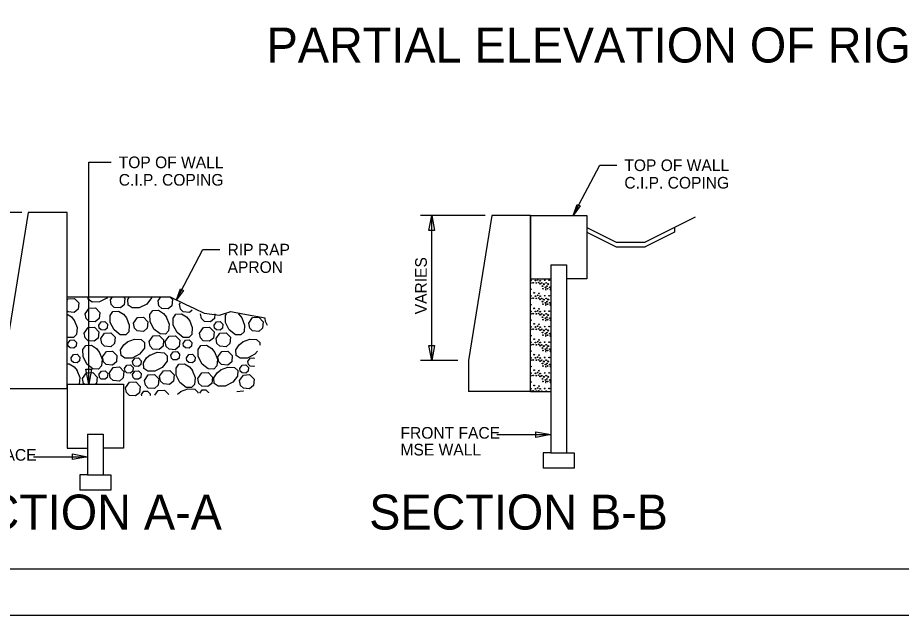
# Model space of a CAD drawing. Extents: x 96 to 240, y 601 to 689.
# Drawn here: x 115.15 to 153.07, y 601 to 626.64 of the extents above; entities that cross this region are included whole.
import ezdxf

# ---------------------------------------------------------------- set-up
doc = ezdxf.new("R2010")
doc.units = 0
for name, color, linetype in [('BR_AUTO DIMENSION', 7, 'Continuous'), ('BR_BORDER LINES', 7, 'Continuous'), ('BR_CONCRETE', 7, 'Continuous'), ('BR_DETAILS', 7, 'Continuous'), ('BR_TEXT', 7, 'Continuous'), ('Level 31', 7, 'Continuous')]:
    doc.layers.add(name, color=color, linetype=linetype)

# ---------------------------------------------------------------- blocks, each defined once
blk = doc.blocks.new('B')
at = {"layer": 'BR_AUTO DIMENSION'}
blk.add_lwpolyline([(-0.2, 0.03), (0, 0), (-0.2, -0.03)], close=True, dxfattribs=at)
blk = doc.blocks.new('ARROW')
at = {"layer": 'BR_AUTO DIMENSION', "xscale": 0.625, "yscale": 0.625}
blk.add_blockref('B', (0, 0), dxfattribs=at)

msp = doc.modelspace()

# ---------------------------------------------------------------- linework, layer by layer
at = {"layer": 'BR_AUTO DIMENSION'}
for p, q in [((118.201, 620.439), (119.163, 620.439)), ((118.201, 610.916), (118.201, 620.439)), ((138.992, 618.156), (140.125, 620.314)), ((140.125, 620.314), (140.856, 620.314)), ((115.328, 618.281), (112.555, 618.281)), ((135.211, 618.156), (132.438, 618.156)), ((132.919, 611.933), (132.919, 618.156)), ((121.969, 614.535), (123.102, 616.693)), ((123.102, 616.693), (123.833, 616.693)), ((134.04, 611.933), (132.438, 611.933)), ((135.718, 608.755), (138.035, 608.755)), ((115.835, 607.809), (118.151, 607.809))]:
    msp.add_line(p, q, dxfattribs=at)
for points in [[(132.794, 617.506), (132.919, 618.156), (133.044, 617.506)], [(133.044, 612.583), (132.919, 611.933), (132.794, 612.583)], [(118.326, 611.566), (118.201, 610.916), (118.076, 611.566)], [(137.385, 608.88), (138.035, 608.755), (137.385, 608.63)], [(117.501, 607.934), (118.151, 607.809), (117.501, 607.684)]]:
    msp.add_lwpolyline(points, close=True, dxfattribs=at)
at = {"layer": 'BR_BORDER LINES'}
msp.add_line((103.173, 603.003), (237.837, 603.003), dxfattribs=at)
at = {"layer": 'BR_CONCRETE'}
for p, q in [((115.608, 618.281), (114.608, 612.058)), ((117.274, 618.281), (115.608, 618.281)), ((117.274, 610.725), (117.274, 618.281)), ((135.491, 618.156), (134.491, 611.933)), ((137.158, 618.156), (135.491, 618.156)), ((137.158, 610.6), (137.158, 618.156)), ((137.158, 618.156), (137.158, 615.437)), ((137.162, 618.156), (139.578, 618.156)), ((139.578, 618.156), (139.578, 615.437)), ((144.222, 618.089), (142.078, 617.017)), ((139.578, 617.642), (140.828, 617.017)), ((143.328, 617.642), (143.328, 617.434)), ((139.578, 617.434), (140.828, 616.809)), ((143.328, 617.434), (142.078, 616.809)), ((140.828, 617.017), (142.078, 617.017)), ((140.828, 616.809), (142.078, 616.809)), ((138.035, 616.041), (138.035, 607.981)), ((138.035, 616.041), (138.701, 616.041)), ((138.701, 616.041), (138.701, 607.981)), ((137.158, 615.437), (138.035, 615.437)), ((139.578, 615.437), (138.701, 615.437)), ((134.491, 611.933), (134.491, 610.6)), ((117.274, 610.916), (119.695, 610.916)), ((117.274, 610.916), (117.274, 608.173)), ((119.695, 610.916), (119.695, 608.173)), ((117.274, 610.725), (114.608, 610.725)), ((137.158, 610.6), (134.491, 610.6)), ((137.158, 610.6), (138.035, 610.6)), ((118.151, 608.777), (118.151, 607.036)), ((118.151, 608.777), (118.818, 608.777)), ((118.818, 608.777), (118.818, 607.036)), ((117.274, 608.173), (118.151, 608.173)), ((119.695, 608.173), (118.818, 608.173)), ((138.035, 607.981), (137.701, 607.981)), ((137.701, 607.981), (137.701, 607.314)), ((138.035, 607.981), (138.701, 607.981)), ((138.701, 607.981), (139.035, 607.981)), ((139.035, 607.981), (139.035, 607.314)), ((118.151, 607.036), (117.818, 607.036)), ((117.818, 607.036), (117.818, 606.369)), ((118.151, 607.036), (118.818, 607.036)), ((118.818, 607.036), (119.151, 607.036)), ((119.151, 607.036), (119.151, 606.369)), ((139.035, 607.314), (137.701, 607.314)), ((119.151, 606.369), (117.818, 606.369))]:
    msp.add_line(p, q, dxfattribs=at)
at = {"layer": 'BR_DETAILS'}
msp.add_line((143.26, 617.4), (143.264, 617.408), dxfattribs=at)
at = {"layer": 'BR_TEXT'}
for p, q in [((117.281, 614.664), (118.364, 614.664)), ((118.364, 614.664), (119.235, 614.664)), ((119.133, 614.54), (119.224, 614.67)), ((119.235, 614.664), (119.703, 614.664)), ((119.703, 614.664), (119.954, 614.664)), ((119.954, 614.664), (121.703, 614.664)), ((121.178, 614.493), (121.302, 614.67)), ((121.703, 614.664), (122.335, 614.359)), ((122.097, 614.347), (122.138, 614.406)), ((122.335, 614.359), (122.746, 614.16)), ((122.746, 614.16), (123.157, 613.961)), ((123.002, 613.94), (123.002, 613.941)), ((123.157, 613.961), (123.817, 613.884)), ((123.817, 613.884), (124.306, 614.032)), ((124.306, 614.032), (124.808, 613.941)), ((124.808, 613.941), (125.773, 613.766)), ((120.479, 610.42), (120.469, 610.471)), ((122.014, 610.492), (122.16, 610.609))]:
    msp.add_line(p, q, dxfattribs=at)
for points in [[(117.274, 614.524), (117.318, 614.586), (117.586, 614.601), (117.773, 614.408), (117.746, 614.137), (117.58, 613.999), (117.315, 614.018), (117.274, 614.058)], [(119.028, 614.67), (118.981, 614.611), (118.659, 614.45), (118.356, 614.444), (118.185, 614.566), (118.178, 614.67)], [(119.689, 614.67), (119.756, 614.601), (119.729, 614.33), (119.563, 614.192), (119.298, 614.212), (119.173, 614.333), (119.133, 614.54)], [(120.898, 614.67), (120.897, 614.623), (120.689, 614.357), (120.367, 614.196), (120.064, 614.19), (119.893, 614.312), (119.877, 614.553), (119.952, 614.67)], [(121.689, 614.67), (121.801, 614.554), (121.774, 614.283), (121.608, 614.146), (121.343, 614.165), (121.218, 614.286), (121.178, 614.493)], [(118.055, 613.94), (118.223, 614.18), (118.491, 614.195), (118.678, 614.001), (118.651, 613.73), (118.485, 613.593), (118.22, 613.612), (118.096, 613.733), (118.055, 613.94)], [(122.641, 614.094), (122.527, 613.999), (122.262, 614.018), (122.137, 614.139), (122.097, 614.347)], [(117.274, 613.924), (117.459, 613.806), (117.585, 613.647)], [(119.819, 613.772), (119.944, 613.457), (119.919, 613.168), (119.788, 613.031), (119.554, 613.036), (119.288, 613.244), (119.127, 613.566), (119.121, 613.869), (119.243, 614.04), (119.485, 614.056), (119.701, 613.918), (119.827, 613.759)], [(121.527, 613.812), (121.652, 613.498), (121.627, 613.209), (121.497, 613.072), (121.262, 613.076), (120.996, 613.285), (120.835, 613.607), (120.83, 613.91), (120.951, 614.081), (121.193, 614.097), (121.409, 613.958), (121.535, 613.8)], [(122.524, 613.66), (122.648, 613.345), (122.624, 613.057), (122.493, 612.919), (122.259, 612.924), (121.992, 613.132), (121.831, 613.454), (121.826, 613.757), (121.947, 613.928), (122.189, 613.944), (122.405, 613.806), (122.532, 613.647)], [(123.619, 613.941), (123.598, 613.73), (123.432, 613.593), (123.167, 613.612), (123.042, 613.733), (123.002, 613.94)], [(124.766, 613.772), (124.891, 613.457), (124.866, 613.168), (124.735, 613.031), (124.501, 613.036), (124.235, 613.244), (124.074, 613.566), (124.068, 613.869), (124.119, 613.941)], [(124.611, 613.941), (124.647, 613.918), (124.774, 613.759)], [(117.577, 613.66), (117.702, 613.345), (117.677, 613.057), (117.546, 612.919), (117.312, 612.924), (117.274, 612.953)], [(118.632, 613.451), (118.733, 613.594), (118.894, 613.603), (119.006, 613.487), (118.99, 613.325), (118.891, 613.242), (118.732, 613.253), (118.657, 613.326), (118.633, 613.451)], [(120.121, 613.534), (120.289, 613.773), (120.558, 613.788), (120.744, 613.595), (120.717, 613.324), (120.551, 613.186), (120.286, 613.205), (120.162, 613.326), (120.121, 613.534)], [(123.579, 613.451), (123.68, 613.594), (123.841, 613.603), (123.953, 613.487), (123.937, 613.325), (123.837, 613.242), (123.678, 613.253), (123.604, 613.326), (123.579, 613.451)], [(125.068, 613.534), (125.236, 613.773), (125.504, 613.788), (125.691, 613.595), (125.664, 613.324), (125.498, 613.186), (125.233, 613.205), (125.109, 613.326), (125.068, 613.534)], [(125.87, 613.431), (125.782, 613.607), (125.779, 613.748)], [(118.008, 613.11), (118.176, 613.349), (118.444, 613.365), (118.631, 613.171), (118.604, 612.9), (118.438, 612.762), (118.173, 612.782), (118.048, 612.902), (118.008, 613.11)], [(118.718, 612.873), (118.886, 613.112), (119.154, 613.127), (119.341, 612.934), (119.314, 612.663), (119.148, 612.525), (118.883, 612.544), (118.759, 612.665), (118.718, 612.873)], [(122.955, 613.11), (123.123, 613.349), (123.391, 613.365), (123.578, 613.171), (123.551, 612.9), (123.385, 612.762), (123.12, 612.782), (122.995, 612.902), (122.955, 613.11)], [(123.665, 612.873), (123.833, 613.112), (124.101, 613.127), (124.288, 612.934), (124.261, 612.663), (124.095, 612.525), (123.83, 612.544), (123.705, 612.665), (123.665, 612.873)], [(117.303, 612.67), (117.404, 612.814), (117.565, 612.823), (117.677, 612.707), (117.661, 612.544), (117.561, 612.462), (117.402, 612.473), (117.327, 612.546), (117.303, 612.67)], [(119.856, 612.733), (120.171, 612.857), (120.46, 612.832), (120.597, 612.702), (120.592, 612.467), (120.384, 612.201), (120.062, 612.04), (119.759, 612.035), (119.588, 612.156), (119.572, 612.398), (119.71, 612.614), (119.869, 612.741)], [(120.794, 612.754), (120.962, 612.994), (121.23, 613.009), (121.417, 612.815), (121.39, 612.544), (121.224, 612.407), (120.959, 612.426), (120.834, 612.547), (120.794, 612.754)], [(121.485, 612.744), (121.653, 612.983), (121.922, 612.999), (122.108, 612.805), (122.081, 612.534), (121.915, 612.396), (121.65, 612.416), (121.526, 612.536), (121.485, 612.744)], [(122.25, 612.67), (122.351, 612.814), (122.512, 612.823), (122.624, 612.707), (122.607, 612.544), (122.508, 612.462), (122.349, 612.473), (122.274, 612.546), (122.25, 612.67)], [(125.441, 612.342), (125.331, 612.201), (125.009, 612.04), (124.705, 612.035), (124.535, 612.156), (124.518, 612.398), (124.657, 612.614), (124.816, 612.741)], [(124.803, 612.733), (125.117, 612.857), (125.406, 612.832), (125.544, 612.702), (125.542, 612.598)], [(118.65, 612.308), (118.775, 611.993), (118.75, 611.704), (118.619, 611.567), (118.385, 611.571), (118.118, 611.78), (117.958, 612.102), (117.952, 612.405), (118.074, 612.576), (118.315, 612.592), (118.531, 612.454), (118.658, 612.295)], [(118.793, 612.086), (118.961, 612.325), (119.229, 612.341), (119.416, 612.147), (119.389, 611.876), (119.223, 611.738), (118.958, 611.758), (118.833, 611.878), (118.793, 612.086)], [(120.832, 612.171), (121.146, 612.296), (121.435, 612.271), (121.572, 612.14), (121.568, 611.906), (121.36, 611.639), (121.038, 611.478), (120.734, 611.473), (120.563, 611.594), (120.547, 611.836), (120.686, 612.052), (120.844, 612.179)], [(121.73, 612.166), (121.831, 612.309), (121.992, 612.319), (122.103, 612.203), (122.087, 612.04), (121.988, 611.957), (121.829, 611.969), (121.754, 612.041), (121.73, 612.166)], [(123.597, 612.308), (123.721, 611.993), (123.696, 611.704), (123.566, 611.567), (123.332, 611.571), (123.065, 611.78), (122.904, 612.102), (122.899, 612.405), (123.02, 612.576), (123.262, 612.592), (123.478, 612.454), (123.605, 612.295)], [(123.74, 612.086), (123.908, 612.325), (124.176, 612.341), (124.363, 612.147), (124.336, 611.876), (124.17, 611.738), (123.905, 611.758), (123.78, 611.878), (123.74, 612.086)], [(117.445, 612.048), (117.546, 612.191), (117.707, 612.2), (117.819, 612.084), (117.803, 611.922), (117.703, 611.839), (117.544, 611.851), (117.469, 611.923), (117.445, 612.048)], [(120.083, 611.89), (120.183, 612.034), (120.344, 612.043), (120.456, 611.927), (120.44, 611.764), (120.341, 611.681), (120.182, 611.693), (120.107, 611.765), (120.083, 611.89)], [(122.392, 612.048), (122.493, 612.191), (122.654, 612.2), (122.766, 612.084), (122.749, 611.922), (122.65, 611.839), (122.491, 611.851), (122.416, 611.923), (122.392, 612.048)], [(125.029, 611.89), (125.13, 612.034), (125.291, 612.043), (125.318, 612.015)], [(117.274, 611.793), (117.364, 611.799), (117.58, 611.661), (117.707, 611.502)], [(119.089, 611.402), (119.257, 611.641), (119.525, 611.657), (119.712, 611.463), (119.685, 611.192), (119.519, 611.054), (119.254, 611.074), (119.129, 611.194), (119.089, 611.402)], [(119.736, 611.599), (119.837, 611.742), (119.998, 611.751), (120.11, 611.635), (120.093, 611.473), (119.994, 611.39), (119.835, 611.401), (119.76, 611.474), (119.736, 611.599)], [(122.646, 611.514), (122.77, 611.2), (122.745, 610.911), (122.615, 610.774), (122.381, 610.778), (122.114, 610.987), (121.953, 611.309), (121.948, 611.612), (122.069, 611.783), (122.311, 611.799), (122.527, 611.661), (122.654, 611.502)], [(123.857, 611.53), (124.172, 611.655), (124.46, 611.63), (124.598, 611.5), (124.593, 611.265), (124.385, 610.999), (124.063, 610.838), (123.759, 610.833), (123.589, 610.954), (123.572, 611.196), (123.711, 611.412), (123.87, 611.538)], [(124.683, 611.599), (124.783, 611.742), (124.944, 611.751), (125.056, 611.635), (125.04, 611.473), (124.941, 611.39), (124.782, 611.401), (124.707, 611.474), (124.683, 611.599)], [(125.318, 611.707), (125.287, 611.681), (125.128, 611.693), (125.054, 611.765), (125.029, 611.89)], [(117.699, 611.514), (117.824, 611.2), (117.799, 610.916)], [(117.941, 611.162), (118.109, 611.401), (118.378, 611.416), (118.564, 611.223), (118.537, 610.952), (118.493, 610.916)], [(118.021, 610.916), (117.982, 610.954), (117.941, 611.162)], [(118.643, 611.337), (118.744, 611.48), (118.905, 611.489), (119.017, 611.373), (119.001, 611.211), (118.902, 611.128), (118.743, 611.14), (118.668, 611.212), (118.644, 611.337)], [(120.083, 611.337), (120.183, 611.48), (120.344, 611.489), (120.456, 611.373), (120.44, 611.211), (120.341, 611.128), (120.182, 611.14), (120.107, 611.212), (120.083, 611.337)], [(120.592, 611.083), (120.76, 611.322), (121.028, 611.337), (121.215, 611.144), (121.188, 610.873), (121.022, 610.735), (120.757, 610.754), (120.632, 610.875), (120.592, 611.083)], [(121.244, 611.258), (121.412, 611.497), (121.68, 611.513), (121.867, 611.319), (121.84, 611.048), (121.674, 610.91), (121.409, 610.93), (121.284, 611.051), (121.244, 611.258)], [(122.888, 611.162), (123.056, 611.401), (123.324, 611.416), (123.511, 611.223), (123.484, 610.952), (123.318, 610.814), (123.053, 610.833), (122.928, 610.954), (122.888, 611.162)], [(124.671, 611.073), (124.839, 611.312), (125.108, 611.328), (125.294, 611.134), (125.267, 610.863), (125.102, 610.725), (124.837, 610.744), (124.712, 610.865), (124.672, 611.073)], [(119.783, 610.764), (119.952, 611.003), (120.22, 611.018), (120.406, 610.825), (120.379, 610.554), (120.214, 610.416), (119.949, 610.435), (119.824, 610.556), (119.784, 610.764)], [(120.469, 610.471), (120.57, 610.615), (120.731, 610.624), (120.843, 610.508), (120.835, 610.437)], [(121.046, 610.447), (121.188, 610.649), (121.456, 610.664), (121.639, 610.474)], [(122.147, 610.601), (122.462, 610.725), (122.751, 610.7), (122.888, 610.57), (122.887, 610.533)], [(122.972, 610.537), (123.065, 610.67), (123.226, 610.679), (123.338, 610.563), (123.337, 610.554)], [(124.563, 610.611), (124.564, 610.612), (124.832, 610.628), (124.836, 610.624)]]:
    msp.add_lwpolyline(points, dxfattribs=at)
for centre, radius in [((137.178, 615.364), 0.0162), ((137.371, 615.362), 0.0162), ((137.465, 615.394), 0.0162), ((137.572, 615.358), 0.0162), ((137.765, 615.377), 0.0162), ((137.956, 615.377), 0.0162), ((137.174, 614.991), 0.0162), ((137.178, 615.262), 0.0162), ((137.269, 615.269), 0.0162), ((137.407, 615.262), 0.0162), ((137.51, 615.278), 0.0162), ((137.571, 615.223), 0.0162), ((137.638, 615.262), 0.0162), ((137.67, 615.12), 0.0162), ((137.691, 615.014), 0.0162), ((137.725, 615.208), 0.0243), ((137.797, 615.074), 0.0162), ((137.83, 615.262), 0.0162), ((137.862, 615.12), 0.0162), ((137.883, 615.014), 0.0162), ((137.916, 615.208), 0.0243), ((137.989, 615.074), 0.0162), ((137.178, 614.702), 0.0162), ((137.178, 614.6), 0.0162), ((137.269, 614.606), 0.0162), ((137.311, 614.837), 0.0162), ((137.371, 614.699), 0.0162), ((137.407, 614.6), 0.0162), ((137.465, 614.731), 0.0162), ((137.51, 614.616), 0.0162), ((137.52, 614.814), 0.0162), ((137.572, 614.695), 0.0162), ((137.571, 614.56), 0.0162), ((137.638, 614.6), 0.0162), ((137.725, 614.545), 0.0243), ((137.765, 614.714), 0.0162), ((137.83, 614.6), 0.0162), ((137.916, 614.545), 0.0243), ((137.956, 614.714), 0.0162), ((137.174, 614.328), 0.0162), ((137.311, 614.175), 0.0162), ((137.67, 614.458), 0.0162), ((137.691, 614.351), 0.0162), ((137.797, 614.411), 0.0162), ((137.862, 614.458), 0.0162), ((137.883, 614.351), 0.0162), ((137.989, 614.411), 0.0162), ((137.178, 614.039), 0.0162), ((137.178, 613.937), 0.0162), ((137.269, 613.944), 0.0162), ((137.371, 614.037), 0.0162), ((137.407, 613.937), 0.0162), ((137.465, 614.068), 0.0162), ((137.51, 613.953), 0.0162), ((137.52, 614.152), 0.0162), ((137.572, 614.032), 0.0162), ((137.571, 613.898), 0.0162), ((137.638, 613.937), 0.0162), ((137.67, 613.795), 0.0162), ((137.725, 613.883), 0.0243), ((137.765, 614.052), 0.0162), ((137.83, 613.937), 0.0162), ((137.862, 613.795), 0.0162), ((137.916, 613.883), 0.0243), ((137.956, 614.052), 0.0162), ((137.174, 613.665), 0.0162), ((137.311, 613.512), 0.0162), ((137.465, 613.406), 0.0162), ((137.52, 613.489), 0.0162), ((137.691, 613.688), 0.0162), ((137.797, 613.748), 0.0162), ((137.883, 613.688), 0.0162), ((137.989, 613.748), 0.0162), ((137.178, 613.376), 0.0162), ((137.178, 613.274), 0.0162), ((137.269, 613.281), 0.0162), ((137.371, 613.374), 0.0162), ((137.407, 613.274), 0.0162), ((137.51, 613.29), 0.0162), ((137.572, 613.369), 0.0162), ((137.571, 613.235), 0.0162), ((137.638, 613.274), 0.0162), ((137.67, 613.132), 0.0162), ((137.691, 613.025), 0.0162), ((137.725, 613.22), 0.0243), ((137.765, 613.389), 0.0162), ((137.797, 613.085), 0.0162), ((137.83, 613.274), 0.0162), ((137.862, 613.132), 0.0162), ((137.883, 613.025), 0.0162), ((137.916, 613.22), 0.0243), ((137.956, 613.389), 0.0162), ((137.989, 613.085), 0.0162), ((137.174, 613.002), 0.0162), ((137.178, 612.714), 0.0162), ((137.311, 612.849), 0.0162), ((137.371, 612.711), 0.0162), ((137.465, 612.743), 0.0162), ((137.52, 612.826), 0.0162), ((137.572, 612.707), 0.0162), ((137.765, 612.726), 0.0162), ((137.956, 612.726), 0.0162), ((137.174, 612.34), 0.0162), ((137.178, 612.611), 0.0162), ((137.269, 612.618), 0.0162), ((137.407, 612.611), 0.0162), ((137.51, 612.627), 0.0162), ((137.571, 612.572), 0.0162), ((137.638, 612.611), 0.0162), ((137.67, 612.47), 0.0162), ((137.691, 612.363), 0.0162), ((137.725, 612.557), 0.0243), ((137.797, 612.423), 0.0162), ((137.83, 612.611), 0.0162), ((137.862, 612.47), 0.0162), ((137.883, 612.363), 0.0162), ((137.916, 612.557), 0.0243), ((137.989, 612.423), 0.0162), ((137.178, 612.051), 0.0162), ((137.178, 611.949), 0.0162), ((137.269, 611.955), 0.0162), ((137.311, 612.186), 0.0162), ((137.371, 612.048), 0.0162), ((137.407, 611.949), 0.0162), ((137.465, 612.08), 0.0162), ((137.51, 611.965), 0.0162), ((137.52, 612.163), 0.0162), ((137.572, 612.044), 0.0162), ((137.571, 611.909), 0.0162), ((137.638, 611.949), 0.0162), ((137.725, 611.894), 0.0243), ((137.765, 612.064), 0.0162), ((137.83, 611.949), 0.0162), ((137.916, 611.894), 0.0243), ((137.956, 612.064), 0.0162), ((137.174, 611.677), 0.0162), ((137.311, 611.524), 0.0162), ((137.67, 611.807), 0.0162), ((137.691, 611.7), 0.0162), ((137.797, 611.76), 0.0162), ((137.862, 611.807), 0.0162), ((137.883, 611.7), 0.0162), ((137.989, 611.76), 0.0162), ((137.178, 611.388), 0.0162), ((137.178, 611.286), 0.0162), ((137.269, 611.293), 0.0162), ((137.371, 611.386), 0.0162), ((137.407, 611.286), 0.0162), ((137.465, 611.417), 0.0162), ((137.51, 611.302), 0.0162), ((137.52, 611.501), 0.0162), ((137.572, 611.381), 0.0162), ((137.571, 611.247), 0.0162), ((137.638, 611.286), 0.0162), ((137.67, 611.144), 0.0162), ((137.725, 611.232), 0.0243), ((137.765, 611.401), 0.0162), ((137.83, 611.286), 0.0162), ((137.862, 611.144), 0.0162), ((137.916, 611.232), 0.0243), ((137.956, 611.401), 0.0162), ((137.174, 611.014), 0.0162), ((137.311, 610.861), 0.0162), ((137.465, 610.755), 0.0162), ((137.52, 610.838), 0.0162), ((137.691, 611.037), 0.0162), ((137.797, 611.097), 0.0162), ((137.883, 611.037), 0.0162), ((137.989, 611.097), 0.0162), ((137.178, 610.725), 0.0162), ((137.178, 610.623), 0.0162), ((137.269, 610.63), 0.0162), ((137.371, 610.723), 0.0162), ((137.407, 610.623), 0.0162), ((137.51, 610.639), 0.0162), ((137.572, 610.718), 0.0162), ((137.638, 610.623), 0.0162), ((137.765, 610.738), 0.0162), ((137.83, 610.623), 0.0162), ((137.956, 610.738), 0.0162)]:
    msp.add_circle(centre, radius, dxfattribs=at)
for centre, start, end in [((137.815, 614.985), 54.7368, 305.2632), ((138.006, 614.985), 54.7368, 305.2632), ((137.815, 614.322), 54.7368, 305.2632), ((138.006, 614.322), 54.7368, 305.2632), ((137.815, 613.659), 54.7368, 305.2632), ((138.006, 613.659), 54.7368, 305.2632), ((137.815, 612.997), 54.7368, 305.2632), ((138.006, 612.997), 54.7368, 305.2632), ((137.815, 612.334), 54.7368, 305.2632), ((138.006, 612.334), 54.7368, 305.2632), ((137.815, 611.671), 54.7368, 305.2632), ((138.006, 611.671), 54.7368, 305.2632), ((137.815, 611.008), 54.7368, 305.2632), ((138.006, 611.008), 54.7368, 305.2632), ((137.571, 610.584), 89.6323, 90.3677)]:
    msp.add_arc(centre, 0.0162, start, end, dxfattribs=at)
at = {"layer": 'Level 31'}
msp.add_lwpolyline([(95.84, 689.004), (95.84, 601.004), (239.84, 601.004), (239.84, 689.004)], dxfattribs=at)

# ---------------------------------------------------------------- block references
at = {"layer": 'BR_TEXT', "xscale": 4.000000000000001, "yscale": 3.999999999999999, "rotation": -117.69914388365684}
for p in [(138.993, 618.156), (121.97, 614.536)]:
    msp.add_blockref('ARROW', p, dxfattribs=at)

# ---------------------------------------------------------------- texts
at = {"layer": 'BR_AUTO DIMENSION'}
msp.add_text('VARIES', height=0.5, rotation=90, dxfattribs=at).set_placement((132.708, 613.917))
for s, p in [('FRONT FACE', (131.579, 608.582)), ('FRONT FACE', (111.695, 607.637)), ('MSE WALL', (131.579, 607.861))]:
    msp.add_text(s, height=0.5, dxfattribs=at).set_placement(p)
at = {"layer": 'BR_TEXT'}
for s, height, p in [('PARTIAL ELEVATION OF RIGID BARRIER', 1.5, (125.836, 624.719)), ('TOP OF WALL', 0.5, (119.49, 620.186)), ('TOP OF WALL', 0.5, (141.184, 620.061)), ('C.I.P. COPING', 0.5, (119.49, 619.436)), ('C.I.P. COPING', 0.5, (141.184, 619.311)), ('RIP RAP', 0.5, (124.161, 616.441)), ('APRON', 0.5, (124.161, 615.691)), ('SECTION A-A', 1.5, (111.098, 604.683)), ('SECTION B-B', 1.5, (130.236, 604.683))]:
    msp.add_text(s, height=height, dxfattribs=at).set_placement(p)

doc.saveas('drawing.dxf')
